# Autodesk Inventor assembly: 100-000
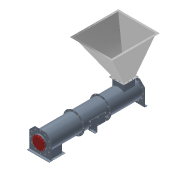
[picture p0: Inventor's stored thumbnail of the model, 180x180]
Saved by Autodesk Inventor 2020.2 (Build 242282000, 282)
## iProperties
Created: 2011-01
Part Number: 100-000
Document SubType Name: Assembly
Designer: F.Stasiak
Description: Podajnik kruszywa
Company: Fabian Stasiak CAD Consulting
Manager: www.cadconsulting.pl
Author: F.Stasiak
Subject: Zbiór ćwiczeń. Autodesk Inventor 2020. Kurs podstawowy
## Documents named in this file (18)
- C:\2020_Kurs_podstawowy\R6 Zespoły\Kolizja\100-000.iam
- C:\2020_Kurs_podstawowy\R6 Zespoły\Kolizja\100-303.ipt
- C:\2020_Kurs_podstawowy\R6 Zespoły\Kolizja\100-210.iam
- C:\2020_Kurs_podstawowy\R6 Zespoły\Kolizja\100-110.iam
- C:\2020_Kurs_podstawowy\R6 Zespoły\Kolizja\Motor_FAN100.ipt
- C:\2020_Kurs_podstawowy\R6 Zespoły\Kolizja\100-304.ipt
- C:\2020_Kurs_podstawowy\R6 Zespoły\Kolizja\100-306.ipt
- C:\2020_Kurs_podstawowy\R6 Zespoły\Kolizja\100-307.ipt
- C:\2020_Kurs_podstawowy\R6 Zespoły\Kolizja\100-305.ipt
- C:\2020_Kurs_podstawowy\R6 Zespoły\Kolizja\100-000\Design Accelerator\Połączenie gwintowe1.iam
- C:\2020_Kurs_podstawowy\R6 Zespoły\Kolizja\100-000\Design Accelerator\Połączenie gwintowe2.iam
- C:\2020_Kurs_podstawowy\R6 Zespoły\Kolizja\100-000\Design Accelerator\Połączenie gwintowe3.iam
- C:\2020_Kurs_podstawowy\R6 Zespoły\Kolizja\100-000\Design Accelerator\Połączenie gwintowe4.iam
- C:\2020_Kurs_podstawowy\R6 Zespoły\Kolizja\100-000\Design Accelerator\Połączenie gwintowe5.iam
- C:\2020_Kurs_podstawowy\R6 Zespoły\Kolizja\100-000\Design Accelerator\Połączenie gwintowe6.iam
- C:\2020_Kurs_podstawowy\R6 Zespoły\Kolizja\100-000\Design Accelerator\Połączenie gwintowe7.iam
- C:\2020_Kurs_podstawowy\R6 Zespoły\Kolizja\100-000\Design Accelerator\Połączenie gwintowe8.iam
- C:\2020_Kurs_podstawowy\R6 Zespoły\Kolizja\100-250.iam
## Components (100 placed, 10 different names)
1. 100-210:1 [sub-assembly] — Zestawiający:7, Równoległy:8, Wstaw:7, Wstaw:8, Zestawiający:17, Zestawiający:18, Zestawiający:24
2. 100-210:2 [sub-assembly] — Zestawiający:8, Zestawiający:9, Zestawiający:10, Zestawiający:12, Zestawiający:13, Zestawiający:14, Zestawiający:19, Zestawiający:20
3. 100-110:1 [sub-assembly] — Zestawiający:12, Zestawiający:13, Zestawiający:14, Równoległy:7, Wstaw:3, Wstaw:4, Równoległy:13, Równoległy:14, Zestawiający:32
4. 100-250:1 [sub-assembly]
5. 100-303:2 — Zestawiający:1, Równoległy:1, Zestawiający:2, Zestawiający:8, Zestawiający:9, Zestawiający:10, Równoległy:5, Równoległy:6, Wstaw:1, Wstaw:2, Równoległy:11, Zestawiający:21, Zestawiający:22, Zestawiający:30
6. 100-303:1 — Zestawiający:1, Równoległy:1, Zestawiający:2, Równoległy:4, Wstaw:5, Wstaw:6, Zestawiający:15, Zestawiający:16, Zestawiający:28
7. Motor_FAN100:1 — Równoległy:4, Wstaw:5, Wstaw:6, Zestawiający:27
8. 100-304:1 — Równoległy:5, Równoległy:6, Wstaw:1, Wstaw:2, Zestawiający:29
9. 100-306:1 — Równoległy:7, Wstaw:3, Wstaw:4, Zestawiający:31
10. 100-307:1 — Równoległy:8, Wstaw:7, Wstaw:8, Zestawiający:23
11. 100-305:1 — Równoległy:11, Równoległy:13, Równoległy:14
12. Połączenie gwintowe:61 [sub-assembly] — Zestawiający:31, Zestawiający:32
13. Połączenie gwintowe:1 [sub-assembly] — Zestawiający:15, Zestawiający:16
14. Połączenie gwintowe:2 [sub-assembly]
15. Połączenie gwintowe:3 [sub-assembly]
16. Połączenie gwintowe:4 [sub-assembly]
17. Połączenie gwintowe:5 [sub-assembly]
18. Połączenie gwintowe:6 [sub-assembly]
19. Połączenie gwintowe:7 [sub-assembly]
20. Połączenie gwintowe:8 [sub-assembly]
21. Połączenie gwintowe:9 [sub-assembly]
22. Połączenie gwintowe:10 [sub-assembly]
23. Połączenie gwintowe:11 [sub-assembly]
24. Połączenie gwintowe:12 [sub-assembly]
25. Połączenie gwintowe:13 [sub-assembly] — Zestawiający:17, Zestawiający:18
26. Połączenie gwintowe:14 [sub-assembly]
27. Połączenie gwintowe:15 [sub-assembly]
28. Połączenie gwintowe:16 [sub-assembly]
29. Połączenie gwintowe:17 [sub-assembly]
30. Połączenie gwintowe:18 [sub-assembly]
31. Połączenie gwintowe:19 [sub-assembly]
32. Połączenie gwintowe:20 [sub-assembly]
33. Połączenie gwintowe:21 [sub-assembly]
34. Połączenie gwintowe:22 [sub-assembly]
35. Połączenie gwintowe:23 [sub-assembly]
36. Połączenie gwintowe:24 [sub-assembly]
37. Połączenie gwintowe:25 [sub-assembly] — Zestawiający:19, Zestawiający:20
38. Połączenie gwintowe:26 [sub-assembly]
39. Połączenie gwintowe:27 [sub-assembly]
40. Połączenie gwintowe:28 [sub-assembly]
41. Połączenie gwintowe:29 [sub-assembly]
42. Połączenie gwintowe:30 [sub-assembly]
43. Połączenie gwintowe:31 [sub-assembly]
44. Połączenie gwintowe:32 [sub-assembly]
45. Połączenie gwintowe:33 [sub-assembly]
46. Połączenie gwintowe:34 [sub-assembly]
47. Połączenie gwintowe:35 [sub-assembly]
48. Połączenie gwintowe:36 [sub-assembly]
49. Połączenie gwintowe:37 [sub-assembly] — Zestawiający:21, Zestawiający:22
50. Połączenie gwintowe:38 [sub-assembly]
51. Połączenie gwintowe:39 [sub-assembly]
52. Połączenie gwintowe:40 [sub-assembly]
53. Połączenie gwintowe:41 [sub-assembly]
54. Połączenie gwintowe:42 [sub-assembly]
55. Połączenie gwintowe:43 [sub-assembly]
56. Połączenie gwintowe:44 [sub-assembly]
57. Połączenie gwintowe:45 [sub-assembly]
58. Połączenie gwintowe:46 [sub-assembly]
59. Połączenie gwintowe:47 [sub-assembly]
60. Połączenie gwintowe:48 [sub-assembly]
61. Połączenie gwintowe:49 [sub-assembly] — Zestawiający:23, Zestawiający:24
62. Połączenie gwintowe:50 [sub-assembly]
63. Połączenie gwintowe:51 [sub-assembly]
64. Połączenie gwintowe:52 [sub-assembly]
65. Połączenie gwintowe:53 [sub-assembly]
66. Połączenie gwintowe:54 [sub-assembly]
67. Połączenie gwintowe:55 [sub-assembly]
68. Połączenie gwintowe:56 [sub-assembly]
69. Połączenie gwintowe:57 [sub-assembly]
70. Połączenie gwintowe:58 [sub-assembly]
71. Połączenie gwintowe:59 [sub-assembly]
72. Połączenie gwintowe:60 [sub-assembly]
73. Połączenie gwintowe:62 [sub-assembly] — Zestawiający:27, Zestawiający:28
74. Połączenie gwintowe:63 [sub-assembly]
75. Połączenie gwintowe:64 [sub-assembly]
76. Połączenie gwintowe:65 [sub-assembly]
77. Połączenie gwintowe:66 [sub-assembly]
78. Połączenie gwintowe:67 [sub-assembly]
79. Połączenie gwintowe:68 [sub-assembly]
80. Połączenie gwintowe:69 [sub-assembly]
81. Połączenie gwintowe:70 [sub-assembly]
82. Połączenie gwintowe:71 [sub-assembly]
83. Połączenie gwintowe:72 [sub-assembly]
84. Połączenie gwintowe:73 [sub-assembly]
85. Połączenie gwintowe:74 [sub-assembly]
86. Połączenie gwintowe:75 [sub-assembly]
87. Połączenie gwintowe:76 [sub-assembly] — Zestawiający:29, Zestawiający:30
88. Połączenie gwintowe:77 [sub-assembly]
89. Połączenie gwintowe:78 [sub-assembly]
90. Połączenie gwintowe:79 [sub-assembly]
91. Połączenie gwintowe:80 [sub-assembly]
92. Połączenie gwintowe:81 [sub-assembly]
93. Połączenie gwintowe:82 [sub-assembly]
94. Połączenie gwintowe:83 [sub-assembly]
95. Połączenie gwintowe:84 [sub-assembly]
96. Połączenie gwintowe:85 [sub-assembly]
97. Połączenie gwintowe:86 [sub-assembly]
98. Połączenie gwintowe:87 [sub-assembly]
99. Połączenie gwintowe:88 [sub-assembly]
100. Połączenie gwintowe:89 [sub-assembly]
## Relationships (42: Mate 25, Flush 9, Insert 8)
- Zestawiający:1 [Mate]: 100-303:2 ↔ 100-303:1
- Równoległy:1 [Flush]: 100-303:2 ↔ 100-303:1
- Zestawiający:2 [Mate]: 100-303:2 ↔ 100-303:1
- Zestawiający:7 [Mate]: 100-210:1
- Zestawiający:8 [Mate]: 100-210:2 ↔ 100-303:2
- Zestawiający:9 [Mate]: 100-210:2 ↔ 100-303:2
- Zestawiający:10 [Mate]: 100-210:2 ↔ 100-303:2
- Zestawiający:12 [Mate]: 100-210:2 ↔ 100-110:1
- Zestawiający:13 [Mate]: 100-210:2 ↔ 100-110:1
- Zestawiający:14 [Mate]: 100-210:2 ↔ 100-110:1
- Równoległy:4 [Flush]: 100-303:1 ↔ Motor_FAN100:1
- Równoległy:5 [Flush]: 100-303:2 ↔ 100-304:1
- Równoległy:6 [Flush]: 100-303:2 ↔ 100-304:1
- Równoległy:7 [Flush]: 100-110:1 ↔ 100-306:1
- Równoległy:8 [Flush]: 100-210:1 ↔ 100-307:1
- Wstaw:1 [Insert]: 100-303:2 ↔ 100-304:1
- Wstaw:2 [Insert]: 100-303:2 ↔ 100-304:1
- Wstaw:3 [Insert]: 100-110:1 ↔ 100-306:1
- Wstaw:4 [Insert]: 100-110:1 ↔ 100-306:1
- Wstaw:5 [Insert]: 100-303:1 ↔ Motor_FAN100:1
- Wstaw:6 [Insert]: 100-303:1 ↔ Motor_FAN100:1
- Wstaw:7 [Insert]: 100-210:1 ↔ 100-307:1
- Wstaw:8 [Insert]: 100-210:1 ↔ 100-307:1
- Równoległy:11 [Flush]: 100-303:2 ↔ 100-305:1
- Równoległy:13 [Flush]: 100-110:1 ↔ 100-305:1
- Równoległy:14 [Flush]: 100-110:1 ↔ 100-305:1
- Zestawiający:15 [Mate]: 100-303:1 ↔ Połączenie gwintowe:1
- Zestawiający:16 [Mate]: 100-303:1 ↔ Połączenie gwintowe:1
- Zestawiający:17 [Mate]: 100-210:1 ↔ Połączenie gwintowe:13
- Zestawiający:18 [Mate]: 100-210:1 ↔ Połączenie gwintowe:13
- Zestawiający:19 [Mate]: 100-210:2 ↔ Połączenie gwintowe:25
- Zestawiający:20 [Mate]: 100-210:2 ↔ Połączenie gwintowe:25
- Zestawiający:21 [Mate]: 100-303:2 ↔ Połączenie gwintowe:37
- Zestawiający:22 [Mate]: 100-303:2 ↔ Połączenie gwintowe:37
- Zestawiający:23 [Mate]: 100-307:1 ↔ Połączenie gwintowe:49
- Zestawiający:24 [Mate]: 100-210:1 ↔ Połączenie gwintowe:49
- Zestawiający:27 [Mate]: Motor_FAN100:1 ↔ Połączenie gwintowe:62
- Zestawiający:28 [Mate]: 100-303:1 ↔ Połączenie gwintowe:62
- Zestawiający:29 [Mate]: 100-304:1 ↔ Połączenie gwintowe:76
- Zestawiający:30 [Mate]: 100-303:2 ↔ Połączenie gwintowe:76
- Zestawiający:31 [Mate]: 100-306:1 ↔ Połączenie gwintowe:61
- Zestawiający:32 [Mate]: 100-110:1 ↔ Połączenie gwintowe:61
